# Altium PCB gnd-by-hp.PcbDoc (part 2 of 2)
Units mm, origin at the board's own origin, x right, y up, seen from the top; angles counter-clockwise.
Board outline 80 x 100 mm, 4 copper layers (Top Layer, Mid-Layer 1, Internal Plane 1, Bottom Layer); 158 components, 114 nets, 565 pads, 335 vias.
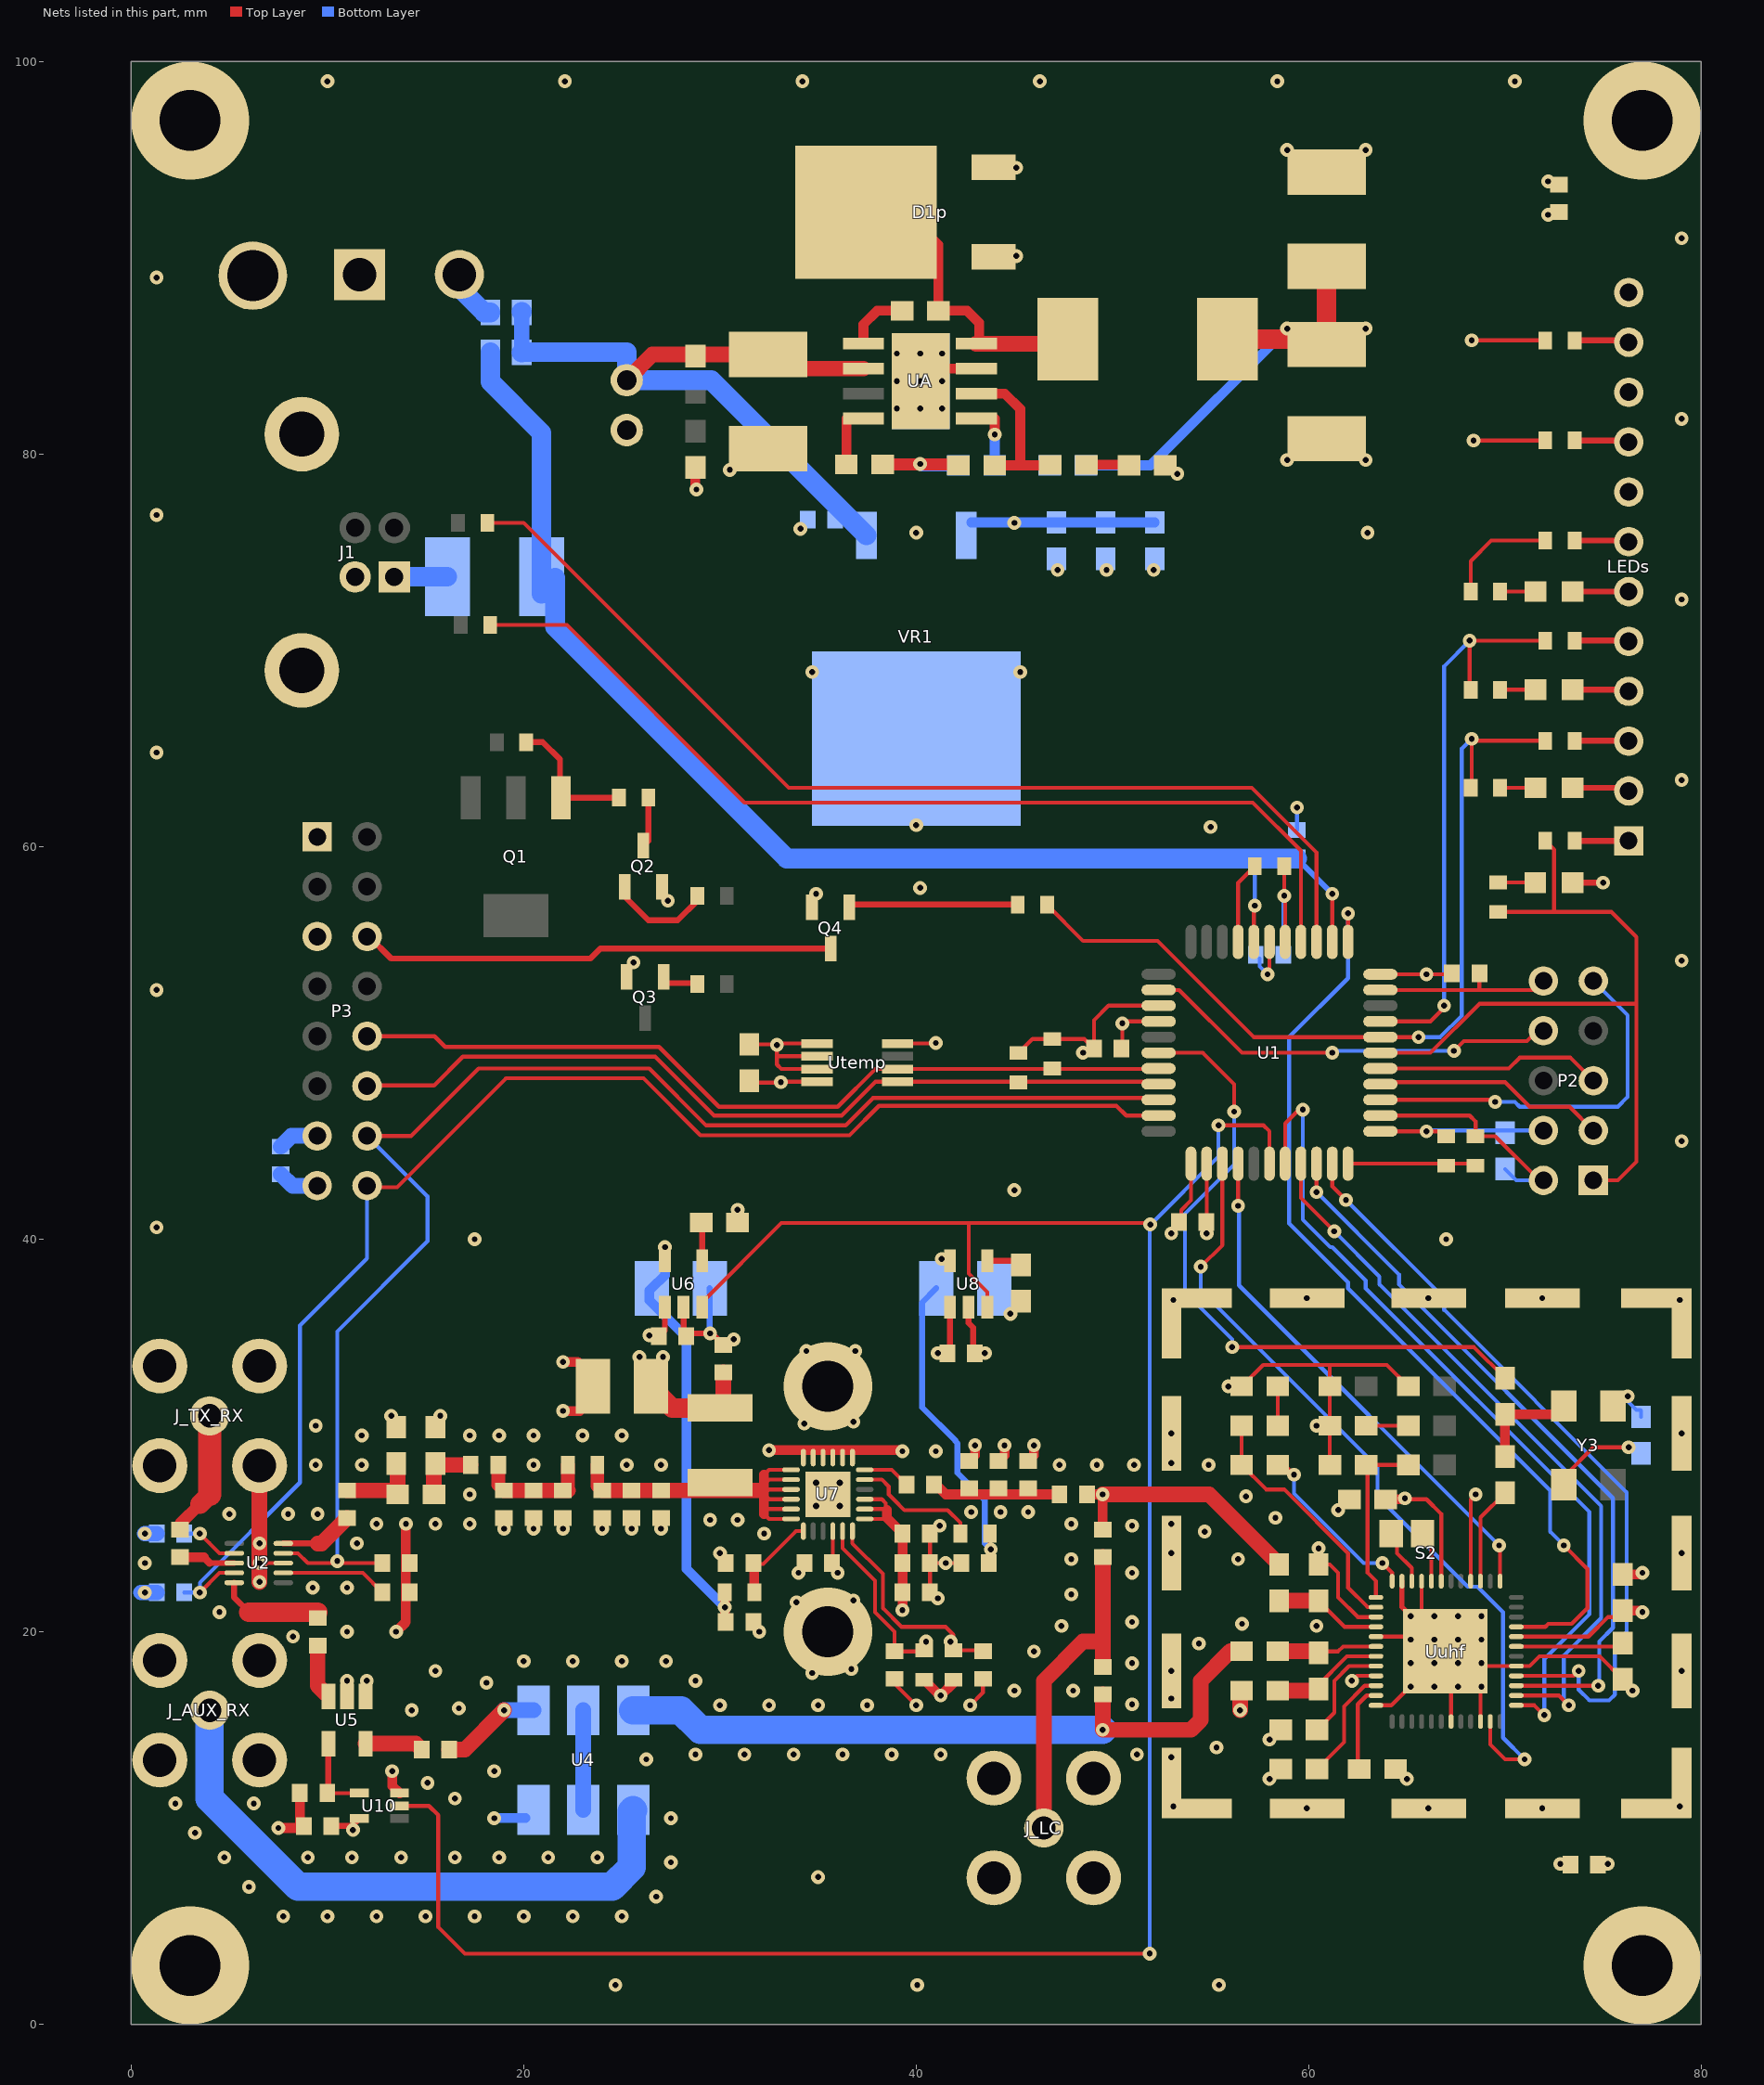
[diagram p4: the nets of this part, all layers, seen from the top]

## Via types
v1: diameter 0.7, hole 0.3, Top Layer to Bottom Layer, 290 vias
v2: diameter 0.7, hole 0.3, Top Layer to Bottom Layer, tented top, 19 vias
v3: diameter 0.6, hole 0.3, Top Layer to Bottom Layer, tented top, 16 vias
v4: diameter 6, hole 3.1, Top Layer to Bottom Layer, 4 vias
v5: diameter 0.66, hole 0.33, Top Layer to Bottom Layer, tented top, 4 vias
v6: diameter 4.5, hole 2.6, Top Layer to Bottom Layer, 2 vias

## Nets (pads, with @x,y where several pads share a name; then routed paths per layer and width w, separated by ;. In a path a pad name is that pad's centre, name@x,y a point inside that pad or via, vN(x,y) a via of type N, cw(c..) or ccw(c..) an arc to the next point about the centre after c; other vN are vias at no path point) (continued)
GND: C2.1 C2p.1 C3.1 C3p.1 C4.1 C4p.1 C5.1 C5p.1 C6.1 C6p.2 C7.2 C8.2 C9.1 C10.1 C11.1 C12h.1 C13.1 C14.1 C15.1 C16.1 C18.2 C19.1 C24.2 C25.2 C26.2 C27.2 C31.1 C32.1 C33.1 C34.1 C35.1 C36.1 C39.2 C40.1 C41.1 C42.2 C43.2 C44.2 C45.2 C45h.1 C46.2 C46h.1 C47.1 C48.2 C49.2 C50.1 C51.1 C52.1 C53.1 C54.1 C55.1 C56.1 C57.1 C59.1 C61.1 C62.1 C64.1 C65.1 C66.2 C67.1 C68.1 C69.1 D1p.1 D1p.3 J1.4 J1.5 J1.6 J_AUX_RX.2 J_AUX_RX.3 J_AUX_RX.4 J_AUX_RX.5 J_LC.2 J_LC.3 J_LC.4 J_LC.5 J_TX_RX.2 J_TX_RX.3 J_TX_RX.4 J_TX_RX.5 L2.1 L3.1 L4.1 P1.1 P2.2 P2.10 P3.1 P3.5 P3.15 pad.0 Q2.2 Q3.2 Q4.2 R3p.1 R4p.1 R5p.2 R11.2 R12.1 R15.1 R29.1 S2.0 U1.5 U1.15 U1.23 U1.35 U1.43 U2.3 U4.6 U5.1 U5.2 U6.2 U7.7 U7.8 U7.9 U7.10 U7.11 U7.12 U7.25 U8.2 U10.3 UA.7 UA.9 Utemp.4 Utemp.5 Utemp.6 Utemp.7 Uuhf.5 Uuhf.12 Uuhf.19 Uuhf.22 Uuhf.29 Uuhf.45 Uuhf.47 Uuhf.49 VR1.2 Y3.2 | length 162.8
  Top Layer w0.2: v1(6.54,23.5) U2.3@7.75,23.5 ; C65.1@31.5,49.925 32.825,49.925 v1@32.9,50 ; 32.925,49.325 Utemp.6@34.95,49.325 ; Utemp.7@34.95,48.675 33.125,48.675 32.9,48.9 v1@32.9,50 ; Utemp.5@34.95,49.975 32.925,49.975 v1@32.9,50 ; C45.2@38.9,17.6 38.9,17.35 v1(40,16.25) ; Utemp.4@39.05,49.975 40.975,49.975 v1(41,50) ; C49.2@40.7,22 C46.2@40.7,23.5 ; C43.2@40.7,25 C46.2@40.7,23.5 ; v1(41.5,23.5) C48.2@42.3,23.5 C46.2@40.7,23.5 ; v1(42.75,16.25) 43.4,16.9 C47.1@43.4,17.6 ; C6.1@50.459,49.708 50.5,49.749 v1(50.5,51) 50.6,51.1 U1.15@52.35,51.1 ; v1(53,40.3) 53.377,40.677 C5.1@53.377,40.869 ; C5.1@53.5,40.9 53.5,41.48 54,41.98 U1.23@54,43.85 ; v1(55.9,32.5) C18.2@56.575,32.5 57.675,33.6 61.1,33.6 ; R29.1@58.75,59 v1(58.75,57.5) 58.8,57.45 U1.5@58.8,55.15 ; v1(60.4,30.5) C56.1@61.075,30.5 ; C57.1@61.075,28.5 C56.1@61.075,30.5 ; v1(61.5,26.2) 61.529,26.2 C59.1@62.075,26.746 ; Uuhf.12@63.425,16.25 64.2,16.25 Uuhf.49@66.95,19 ; Uuhf.5@63.425,19.75 65.05,19.75 v3(65.2,19.6) ; U1.35@63.65,46.3 68.2,46.3 68.5,46 R15.1@68.5,45.25 69.5,45.25 71.75,43 P2.2@71.96,43 ; U1.43@63.65,52.7 68.7,52.7 ; C15.1@65.075,32.5 63.975,33.6 61.1,33.6 ; Uuhf.45@65.75,22.575 65.75,20.2 Uuhf.49@66.95,19 ; Uuhf.19@67.25,15.425 67.25,18.7 Uuhf.49@66.95,19 ; C8.2@68.696,53.543 68.696,52.704 68.7,52.7 ; Uuhf.22@68.75,15.425 68.75,17.15 v3(68.8,17.2) ; P2.10@71.96,53.16 71.5,52.7 68.7,52.7 ; v1(72.2,93.9) 72.36,93.74 C9.1@72.746,93.74 ; v1(72.822,8.166) 72.847,8.141 C68.1@73.341,8.141 ; C10.1@76,17.575 74.825,18.75 71.75,18.75 71.25,18.25 Uuhf.29@70.575,18.25 67.7,18.25 Uuhf.49@66.95,19 ; C56.1@61.075,30.5 C55.1@61.075,32.5 61.075,33.575 61.1,33.6
  Top Layer w0.25: Uuhf.47@64.75,22.575 64.75,21.25 v3(65.2,20.8)
  Top Layer w0.3: U6.2@28.143,36.544 28.143,35.193 C54.1@28.284,35.052 28.432,35.2 v1(29.5,35.2) 29.584,35.2 C51.1@30.175,34.609 ; C19.1@30.897,40.843 30.897,41.597 v1@30.9,41.6 ; U8.2@42.672,36.544 42.672,35.728 42.9,35.5 42.9,34.279 C53.1@42.966,34.214 ; C53.1@42.991,34.188 43.488,34.188 v1(43.5,34.2) ; v1(44.8,36.2) 45.339,36.739 C52.1@45.339,36.845
  Top Layer w0.5: v1(7.5,10) C67.1@8.705,10 ; C67.1@8.596,10.108 C66.2@8.596,11.786 ; v1(13.3,12.9) 13.3,12.149 U10.3@13.674,11.775 ; v1(13.5,20) 14,20.5 v1(14,25.5) ; v2(22,31.25) 22.85,31.25 C42.2@23.525,31.925 ; v2(22,33.75) 22.75,33.75 23.525,32.975 C42.2@23.525,32.5 ; R4p.1@28.751,79.32 28.751,78.249 v1(28.8,78.2) ; v1(32.5,29.25) 39.25,29.25 v1(39.3,29.2) ; Q4.2@34.69,56.905 34.69,57.39 v1(34.9,57.6) ; UA.9@40.232,83.725 40.867,84.36 UA.7@43.061,84.36 ; L2.1@42.7,28.7 43,29 v1(43,29.5) ; L3.1@44.2,28.7 44.5,29 v1(44.5,29.5) ; L4.1@45.7,28.7 46,29 v1(46,29.5) ; C11.1@76,22.925 76.925,22.925 v1(77,23)
  Top Layer w0.6: C5p.1@38.288,79.477 42.107,79.477 C6p.2@42.151,79.432
  Top Layer w0.8: v1(6.54,22.54) v1(6.54,23.5) v1(6.54,24.5) J_TX_RX.3@6.54,28.46 ; v1(56.5,16) 56.5,16.925 C12h.1@56.575,17
  Bottom Layer w0.2: C7.2@58.7,54.5 58.7,57.45 v1(58.75,57.5) ; C69.1@59.394,60.847 59.4,60.853 v1(59.4,62) ; C13.1@70,43.575 70.575,43 P2.2@71.96,43 ; v2(76.25,32) 76.25,31.75 76.7,31.3 76.9,31.3 76.937,31.263 C16.1@76.937,30.948
  Bottom Layer w0.3: C39.2@29.475,37.5 29.475,35.225 v1(29.5,35.2)
  Bottom Layer w0.5: v1(18.5,10.5) U4.6@20.08,10.5
  Bottom Layer w0.6: v1@40.268,79.432 R3p.1@42.151,79.432
  Bottom Layer w0.8: v1(0.7,22) C27.2@1.3,22 ; v1(0.7,25) C26.2@1.3,25 ; C64.1@7.626,43.318 8.221,42.723 P3.15@9.48,42.723
  other v1: 24.675,2 40.051,2 55.426,2 7.75,5.5 10,5.5 12.5,5.5 15,5.5 17.5,5.5 20,5.5 22.5,5.5 25,5.5 26.75,6.5 6,7 35,7.5 27.5,8.25 4.75,8.5 9,8.5 11.25,8.5 13.75,8.5 16.5,8.5 18.75,8.5 21.25,8.5 23.75,8.5 27.5,10.5 16.5,11.5 15.1,12.3 58,12.5 65,12.5 18.5,12.9 26.25,13.5 53,13.6 28.75,13.75 31.25,13.75 33.75,13.75 36.25,13.75 38.75,13.75 41.25,13.75 51.25,13.75 55.3,14.1 58,14.5 30,16.25 32.5,16.25 35,16.25 37.5,16.25 51,16.3 53,16.6 45,17 48,17 76.5,17 18.1,17.4 28.75,17.5 34.7,17.9 15.5,18 36.7,18.1 51,18.4 20,18.5 22.5,18.5 25,18.5 27.25,18.5 46,19 54.4,19.4 8.25,19.75 11,20 32,20 47.4,20.3 60.4,20.3 56.6,20.4 51,20.5 4.5,21 33.9,21.5 36.8,21.6 41.1,21.7 47.9,21.9 9.25,22.25 11,22.25 34,23 51,23 0.7,23.5 47.9,23.7 56.4,23.7 30,24 11.5,24.5 32.25,25 54.7,25.1 19,25.25 20.5,25.25 22,25.25 24,25.25 25.5,25.25 27,25.25 41.2,25.4 51,25.4 12.5,25.5 15.5,25.5 17.25,25.5 47.9,25.5 53,25.5 29.5,25.7 30.9,25.7 58.3,25.8 5,26 8,26 9.5,26 42.8,26.1 44.3,26.1 45.7,26.1 56.8,26.9 17.25,27 9.4,28.5 11.75,28.5 20.5,28.5 25.25,28.5 27,28.5 47.3,28.5 49.2,28.5 51.1,28.5 54.9,28.5 53,28.6 41,29.2 11.75,30 17.25,30 18.75,30 20.5,30 23,30 25,30 9.4,30.5 34.3,30.6 36.8,30.7 13.25,31 15.75,31 34.4,34.3 36.9,34.3 30.7,34.9 17.5,40 67,40 1.3,40.6 30.9,41.5 45,42.5 79,45 32.9,49.9 1.3,52.7 25.6,54.1 79,54.2 27.35,57.25 40.2,57.9 55,61 40,61.1 79,63.4 1.3,64.8 34.7,68.9 45.3,68.9 79,72.6 47.2,74.1 49.7,74.1 52.1,74.1 40,76 63,76 34.1,76.2 1.3,76.9 53.3,79 30.5,79.2 40.2,79.5 58.9,79.7 62.9,79.7 79,81.8 1.3,89 45.1,90.1 79,91 45.1,94.6 58.9,95.5 62.9,95.5 10,99 22.1,99 34.2,99 46.3,99 58.4,99 70.5,99
  other v2: 3.25,9.75 2.25,11.25 6.25,11.25 14.3,16 16.7,16.1 11,17.5 12,17.5
  other v3: 65.2,17.2 66.4,17.2 67.6,17.2 65.2,18.4 66.4,18.4 67.6,18.4 68.8,18.4 66.4,19.6 67.6,19.6 68.8,19.6 66.4,20.8 67.6,20.8 68.8,20.8
  other v4: 3,3 77,3 3,97 77,97
  other v5: 34.9,26.4 36.1,26.4 34.9,27.6 36.1,27.6
  other v6: 35.5,20 35.5,32.5
L1: L5.1 Uuhf.46 | length 2.9
  Top Layer w0.2: L5.1@64.2,25 64.5,24.7 64.5,24 65.25,23.25 Uuhf.46@65.25,22.575
L2: L5.2 Uuhf.44 | length 2.6
  Top Layer w0.2: L5.2@65.8,25 66.25,24.55 Uuhf.44@66.25,22.575
LED_P: R5.1 R19.2 U1.41 | length 29.3
  Top Layer w0.2: U1.41@63.65,51.1 66.2,51.1 67,51.9 v1(66.9,51.9) ; R19.2@68.25,68 68.2,68.05 v1(68.2,70.5) R5.1@72.05,70.5
  Bottom Layer w0.2: v1(66.9,51.9) 66.9,69.2 v1(68.2,70.5)
LED_R: R4.1 R18.2 R34.2 U1.40 | length 45.2
  Top Layer w0.2: R34.2@46.662,57.038 48.5,55.2 52.3,55.2 57.2,50.3 U1.40@63.65,50.3 v1(65.6,50.3) ; R18.2@68.25,63 68.2,63.05 68.3,63.15 v1@68.3,65.4 ; R4.1@72.05,65.4 v1@68.3,65.4 ; v1@68.3,65.4 v1(68.3,65.5) 68.2,65.4 v1@68.3,65.4
  Bottom Layer w0.2: v1(65.6,50.3) 66.7,50.3 67.8,51.4 67.8,65 v1(68.3,65.5)
LED_T: P2.1 R3.1 R17.2 U1.39 | length 39.5
  Top Layer w0.2: U1.39@63.65,49.5 66.2,49.5 68.7,52 76.7,52 ; R17.2@69.647,56.679 72.5,56.679 ; R3.1@72.05,60.3 72.5,59.85 72.5,56.679 ; P2.1@74.5,43 75.75,43 76.7,43.95 76.7,52 ; 72.5,56.679 75.421,56.679 76.7,55.4 76.7,52
LED_U1: P2.3 R6.1 R20.2 U1.37 | length 17.7
  Top Layer w0.2: U1.37@63.65,47.9 63.75,48 70,48 71.25,46.75 73.29,46.75 P2.3@74.5,45.54 ; R20.2@68.25,73 68.25,74.55 69.3,75.6 R6.1@72.05,75.6
LED_U2: R7.1 | length 3.7
  Top Layer w0.2: v1(68.4,80.7) R7.1@72.05,80.7
LED_U3: R8.1 | length 3.8
  Top Layer w0.2: v1(68.3,85.8) R8.1@72.05,85.8
LNA_V: C66.1 U5.4 U10.4 | length 4.3
  Top Layer w0.2: C66.1@10.05,12.045 9.881,11.876 9.981,11.775 U10.4@11.624,11.775
  Top Layer w0.3: C66.1@10.05,12.045 U5.4@10.05,14.3
MUXOUT: U1.26 Uuhf.37 | length 26.8
  Top Layer w0.2: v1(56.4,41.7) U1.26@56.4,43.85 ; v1(69.7,24.4) 69.75,24.35 Uuhf.37@69.75,22.575
  Bottom Layer w0.2: v1(56.4,41.7) 56.45,41.65 56.45,37.65 v1(69.7,24.4)
NetC1p_1: C1p.1 UA.1 | length 3.2
  Top Layer w0.5: UA.1@37.311,85.63 37.311,86.589 37.3,86.6 38.006,87.306 C1p.1@39.281,87.306
NetC5p_2: C5p.2 UA.4 | length 2.3
  Top Layer w0.5: C5p.2@36.438,79.477 UA.4@36.438,81.8
NetC6p_1: C6p.1 C7p.1 UA.6 | length 8.2
  Top Layer w0.5: UA.6@43.061,83.09 44.51,83.09 45.3,82.3 45.3,79.5 ; C6p.1@44.001,79.432 46.8,79.432 C7p.1@46.825,79.458
NetC7_1: C7.1 U1.6 | length 2.3
  Top Layer w0.2: v2@58,53.8 58,54 U1.6@58,55.15
  Bottom Layer w0.2: C7.1@57.5,54.3 57.5,53.9 v2(57.9,53.5)
NetC7p_2: C7p.2 R5p.1 | length 2.2
  Top Layer w0.5: C7p.2@48.675,79.458 50.813,79.458 R5p.1@50.838,79.432
NetC9h_2: C9h.2 L1h.2 Uuhf.6 | length 5.2
  Top Layer w0.2: L1h.2@60.425,19 61.5,19 61.75,19.25 Uuhf.6@63.425,19.25
  Top Layer w0.8: C9h.2@58.425,19 60.425,19 L1h.2@60.5,18.925
NetC10_2: C10.2 Uuhf.31 | length 5.5
  Top Layer w0.2: Uuhf.31@70.575,19.25 75.825,19.25 C10.2@76,19.425
NetC12_2: C12.2 U5.5 | length 3
  Top Layer w0.8: U5.5@11.95,14.3 14.5,14.3 C12.2@14.8,14
NetC12h_2: C12h.2 L1h.1 Uuhf.7 | length 5.9
  Top Layer w0.2: L1h.1@60.425,17 60.425,17.225 61.95,18.75 Uuhf.7@63.425,18.75
  Top Layer w0.8: C12h.2@58.425,17 L1h.1@60.425,17
NetC14_2: C14.2 Uuhf.11 | length 4.4
  Top Layer w0.2: C14.2@62.575,13 62.5,13.075 62.5,16.3 62.95,16.75 Uuhf.11@63.425,16.75
NetC17_1: C17.1 R13.1 Uuhf.2 | length 12.9
  Top Layer w0.2: R13.1@56.575,30.5 C17.1@56.575,28.5 57.825,27.25 58.75,27.25 62,24 62,22.25 63,21.25 Uuhf.2@63.425,21.25
NetC17_2: C17.2 Uuhf.48 | length 9.1
  Top Layer w0.2: C17.2@58.425,28.5 58.75,28.5 v1(59.25,28) ; v1(63.75,23.5) 64.25,23 Uuhf.48@64.25,22.575
  Bottom Layer w0.2: v1(59.25,28) 59.25,27.05 62.8,23.5 v1(63.75,23.5)
NetC18_1: C18.1 R13.2 | length 2
  Top Layer w0.2: R13.2@58.425,30.5 C18.1@58.425,32.5
NetC19_2: C19.2 U6.4 | length 2
  Top Layer w0.3: C19.2@29.047,40.843 29.093,40.797 U6.4@29.093,38.894
NetC20_1: C20.1 C30.1 Y3.3 | length 5.3
  Top Layer w0.5: C30.1@70,28.925 C20.1@70,31.075 72.575,31.075 Y3.3@73,31.5
NetC21_1: C21.1 C46h.2 L5h.2 | length 4.3
  Top Layer w0.8: C21.1@11,27.2 13.375,27.2 L5h.2@13.575,27 13.575,28.5 C46h.2@13.5,28.575
NetC21_2: C21.2 U2.5 | length 3.8
  Top Layer w0.3: U2.5@7.75,24.5 9.5,24.5
  Top Layer w0.8: 9.5,24.5 9.7,24.5 C21.2@11,25.8
NetC22_1: C22.1 U2.8 | length 2.9
  Top Layer w0.3: 4,23.5 U2.8@5.25,23.5
  Top Layer w0.4: 3.7,23.8 4,23.5
  Top Layer w0.5: C22.1@2.5,23.8 3.7,23.8
NetC23_1: C23.1 U5.3 | length 2.6
  Top Layer w0.8: C23.1@9.5,19.3 9.5,17.25 U5.3@9.875,16.875
NetC24_1: C24.1 U2.2 | length 5.5
  Top Layer w0.2: U2.2@7.75,23 11.8,23 C24.1@12.8,22
NetC26_1: C26.1 U2.7 | length 3
  Top Layer w0.2: v1(3.5,25) 4,24.5 4.5,24 U2.7@5.25,24
  Bottom Layer w0.2: C26.1@2.7,25 v1(3.5,25)
NetC29_1: C29.1 C34.2 C35.2 C36.2 R16.2 | length 6
  Top Layer w0.5: C36.2@18.7,27.5 C36.2@19,27.2
  Top Layer w0.7: C36.2@18.7,27.5 C29.1@18.7,28.5 ; C34.2@22.25,27.2 R16.2@22.25,28.5
  Top Layer w0.8: C36.2@19,27.2 C35.2@20.5,27.2 C34.2@22.25,27.2
NetC30_2: C30.2 Uuhf.39 | length 5
  Top Layer w0.2: Uuhf.39@68.75,22.575 68.75,25.825 C30.2@70,27.075
NetC37_1: C37.1 C38.2 L2.2 L3.2 L4.2 | length 6.6
  Top Layer w0.5: C38.2@40.9,27.5 41,27.5 41.5,27 45,27 C37.1@47.3,27
NetC38_1: C38.1 U7.6 | length 2.4
  Top Layer w0.2: U7.6@37.375,28.25 38.75,28.25 C38.1@39.5,27.5
NetC42h_1: C42h.1 L4h.1 Uuhf.4 | length 5.5
  Top Layer w0.2: L4h.1@60.5,21.575 61.825,20.25 Uuhf.4@63.425,20.25
  Top Layer w0.8: C42h.1@58.5,21.575 L4h.1@60.5,21.575
NetC45_1: C45.1 R21.1 U7.23 | length 8.7
  Top Layer w0.2: U7.23@36.25,25.125 36.25,24.25 37.9,22.6 37.9,21 38.9,20 C45.1@38.9,19 40.35,19 R21.1@40.4,19.05
  other v1: 40.5,19.5
NetC47_2: C47.2 R22.1 U7.24 | length 11
  Top Layer w0.2: U7.24@36.75,25.125 36.75,24.5 38.3,22.95 38.3,21.2 39.25,20.25 41.5,20.25 41.9,19.85 R22.1@41.9,19.05 43.35,19.05 C47.2@43.4,19
  other v1: 41.75,19.5
NetC50_2: C50.2 R23.2 U7.19 | length 4.7
  Top Layer w0.2: C50.2@31.75,23.45 32.2,23.45 33.875,25.125 U7.19@34.25,25.125
  Top Layer w0.5: C50.2@31.7,23.5 31.75,23.45 R23.2@31.75,22
NetC52_2: C52.2 U8.4 | length 1.8
  Top Layer w0.3: U8.4@43.622,38.894 45.14,38.894 C52.2@45.339,38.695
NetC56_2: C56.2 R9.1 | length 2.2
  Top Layer w0.2: C56.2@62.925,30.5 R9.1@65.075,30.5
NetD1_2: D1.2 R17.1 | length 1.9
  Top Layer w0.2: R17.1@69.647,58.179 71.528,58.179 D1.2@71.542,58.166
NetD2_2: D2.2 R18.1 | length 1.8
  Top Layer w0.2: R18.1@69.75,63 D2.2@71.55,63
NetD3_2: D3.2 R19.1 | length 1.8
  Top Layer w0.2: R19.1@69.75,68 D3.2@71.55,68
NetD4_2: D4.2 R20.1 | length 1.8
  Top Layer w0.2: R20.1@69.75,73 D4.2@71.55,73
NetJ1_1: J1.1 MF.2 | length 2.7
  Bottom Layer w0.2: J1.1@13.41,73.75 J1.1@13.42,73.76
  Bottom Layer w1: J1.1@13.42,73.76 MF.2@16.111,73.76
NetLEDs_1: LEDs.1 R3.2 | length 2.7
  Top Layer w0.3: R3.2@73.55,60.3 LEDs.1@76.3,60.3
NetLEDs_3: LEDs.3 R4.2 | length 2.8
  Top Layer w0.3: R4.2@73.55,65.4 76.28,65.4 LEDs.3@76.3,65.38
NetLEDs_5: LEDs.5 R5.2 | length 2.8
  Top Layer w0.3: R5.2@73.55,70.5 76.26,70.5 LEDs.5@76.3,70.46
NetLEDs_7: LEDs.7 R6.2 | length 2.8
  Top Layer w0.3: R6.2@73.55,75.6 76.24,75.6 LEDs.7@76.3,75.54
NetLEDs_9: LEDs.9 R7.2 | length 2.8
  Top Layer w0.3: R7.2@73.55,80.7 76.22,80.7 LEDs.9@76.3,80.62
NetLEDs_11: LEDs.11 R8.2 | length 2.8
  Top Layer w0.3: R8.2@73.55,85.8 76.2,85.8 LEDs.11@76.3,85.7
NetQ1_1: Q1.1 R25.1 R26.1 | length 7
  Top Layer w0.3: R25.1@20.13,65.329 20.971,65.329 21.85,64.45 21.85,62.55 Q1.1@21.9,62.5 R26.1@24.85,62.5
NetQ2_1: Q2.1 R27.1 | length 5.4
  Top Layer w0.3: Q2.1@25.15,57.95 25.15,57.45 26.35,56.25 27.85,56.25 28.85,57.25 R27.1@28.85,57.5
NetQ2_3: Q2.3 R26.2 | length 2.6
  Top Layer w0.3: Q2.3@26.1,60.05 26.35,60.3 R26.2@26.35,62.5
NetQ3_1: Q3.1 R28.1 | length 1.7
  Top Layer w0.3: Q3.1@27.15,53.05 28.8,53.05 R28.1@28.85,53
NetQ4_1: Q4.1 R34.1 | length 8.7
  Top Layer w0.3: Q4.1@36.59,56.905 36.734,57.048 R34.1@45.2,57.048
NetR1_2: R1.2 U1.3 | length 53.8
  Top Layer w0.2: R1.2@18.15,76.5 20,76.5 33.5,63 57.1,63 60.4,59.7 U1.3@60.4,55.15
NetR2_2: R2.2 U1.4 | length 50.7
  Top Layer w0.2: R2.2@18.296,71.296 22.204,71.296 31.25,62.25 57.15,62.25 59.6,59.8 U1.4@59.6,55.15
NetR11_1: R11.1 Uuhf.8 | length 5.3
  Top Layer w0.2: R11.1@60.425,15 61.3,15.875 61.3,17.5 62.05,18.25 Uuhf.8@63.425,18.25
NetR12_2: R12.2 Uuhf.10 | length 5.8
  Top Layer w0.2: R12.2@60.425,13 61.8,14.375 61.8,16.2 62.85,17.25 Uuhf.10@63.425,17.25
NetR24_1: R24.1 U7.5 | length 6.6
  Top Layer w0.2: U7.5@37.375,27.75 38.25,27.75 38.6,27.4 38.6,27 38.9,26.7 39.4,26.2 41.6,26.2 42.25,25.55 R24.1@42.25,25
NetR29_2: R29.2 U1.8 | length 4.2
  Top Layer w0.2: U1.8@56.4,55.15 56.4,58.15 R29.2@57.25,59
NetU4_2: U4.2 U4.5 | length 5.1
  Bottom Layer w0.8: U4.5@23.04,10.92 U4.2@23.04,16
PA_BIAS_EN: U1.28 U6.3 U8.3 U10.2 | length 122.4
  Top Layer w0.2: U10.2@13.674,11.125 15.175,11.125 15.65,10.65 15.65,4.95 17,3.6 v1(51.9,3.6) ; U6.3@29.093,36.407 U6.3@29.093,36.544 29.093,36.793 33.125,40.825 42.675,40.825 ; U8.3@43.7,36.466 U8.3@43.622,36.544 43.622,37.303 42.675,38.25 42.675,40.825 ; v1(51.925,40.75) 51.85,40.825 42.675,40.825 ; v1(55.4,45.8) 57.7,45.8 58,45.5 U1.28@58,43.85
  Bottom Layer w0.2: v1(51.9,3.6) 51.9,40.7 55.4,44.2 v1(55.4,45.8)
PA_IN: C28.1 C37.2 C42h.2 | length 13.1
  Top Layer w0.5: C37.2@48.7,27 v1(49.5,27) C28.1@49.5,25.2
  Top Layer w0.8: v1(49.5,27) 54.925,27 C42h.2@58.5,23.425
PA_OUT: C29.2 C45h.2 L5h.1 | length 3.4
  Top Layer w0.8: L5h.1@15.425,27 15.425,28.5 C45h.2@15.5,28.575 15.575,28.5 C29.2@17.3,28.5
PE2: R14.1 R15.2 U1.33 | length 6.5
  Top Layer w0.2: U1.33@62,43.85 68.4,43.85 R15.2@68.5,43.75
PHA: C1p.2 D1p.4 LA.1 UA.8 | length 12.3
  Top Layer w0.5: D1p.4@40.6,91.2 41.131,90.669 C1p.2@41.131,87.306 42.594,87.306 43.2,86.7 43.2,85.769 UA.8@43.061,85.63
  Top Layer w0.8: UA.8@43.061,85.63 47.496,85.63 LA.1@47.725,85.859
PTT_TX_STAGE_1: P3.6 Q4.3 | length 24.2
  Top Layer w0.3: P3.6@12.12,55.423 13.243,54.3 23.4,54.3 23.905,54.805 Q4.3@35.64,54.805
RESET: P2.8 U1.13 | length 21.4
  Top Layer w0.2: U1.13@52.35,52.7 53.4,52.7 56.6,49.5 v1(61.2,49.5) ; v1(67.4,49.6) 67.9,50.1 71.11,50.1 71.63,50.62 P2.8@71.96,50.62
  Bottom Layer w0.2: v1(61.2,49.5) 61.3,49.6 v1(67.4,49.6)
RF_LC: C28.2 C58.2 J_LC.1 | length 16.9
  Top Layer w0.8: J_LC.1@46.5,10 46.5,17.5 48.5,19.5 49.5,19.5 ; C58.2@49.5,18.2 49.5,19 C28.2@49.5,23.8
RF_RX: C23.2 U2.10 | length 5.3
  Top Layer w0.3: U2.10@5.25,22.5 5.25,21.75 6,21
  Top Layer w1: 6,21 C23.2@9.5,21
RF_RX_AUX: J_AUX_RX.1 U4.4 | length 31.2
  Bottom Layer w1.44: J_AUX_RX.1@4,16 4,11.5 8.5,7 24.5,7 25.5,8 25.5,10.84 U4.4@25.58,10.92
RF_RX_C: C27.1 P3.16 U1.21 U2.9 | length 72
  Top Layer w0.2: v1(3.5,22) 4.5,23 U2.9@5.25,23 ; P3.16@11.9,42.653 13.553,42.653 19.1,48.2 26.1,48.2 29,45.3 36.6,45.3 38.1,46.8 50.2,46.8 50.7,46.3 U1.21@52.35,46.3
  Bottom Layer w0.2: C27.1@2.7,22 v1(3.5,22) 3.5,22.5 8.6,27.6 8.6,35.6 12.02,39.02 P3.16@12.02,42.723
RF_RX_LNA: C12.1 U4.1 | length 5.1
  Top Layer w0.8: C12.1@16.2,14 17,14 v1(19,16)
  Bottom Layer w0.8: v1(19,16) U4.1@20.5,16
RF_RX_MOD: C9h.1 C58.1 U4.3 | length 36
  Top Layer w0.8: C58.1@49.5,16.8 v1(49.5,15) 54,15 54.5,15.5 54.5,17.5 56,19 C9h.1@56.575,19
  Bottom Layer w1.44: U4.3@25.58,16 28,16 29,15 v1(49.5,15)
RF_RX_TX: C22.2 J_TX_RX.1 | length 6.4
  Top Layer w0.5: C22.2@2.5,25.2 C22.2@2.5,25.5
  Top Layer w0.6: C22.2@2.5,25.5 3.5,26.5
  Top Layer w1: 3.5,26.5 4,27
  Top Layer w1.2: 4,27 J_TX_RX.1@4,31
RF_TX_C: C25.1 P3.14 U1.20 U2.4 | length 73.7
  Top Layer w0.2: U2.4@7.75,24 8.5,24 9,23.5 C25.1@12.8,23.5 ; P3.14@12.02,45.263 14.263,45.263 17.7,48.7 26.4,48.7 29.3,45.8 36.4,45.8 37.8,47.2 52.25,47.2 U1.20@52.35,47.1
  Bottom Layer w0.2: v1(10.5,23.6) 10.5,35.3 15.1,39.9 15.1,42.183 P3.14@12.02,45.263
RFOUT: C31.2 C32.2 C33.2 L1.1 R16.1 U7.13 U7.14 U7.15 U7.16 U7.17 U7.18 | length 20.7
  Top Layer w0.2: 32.25,26 32.5,25.75 U7.18@33.625,25.75 ; 32.25,26.25 U7.17@33.625,26.25 ; 32.25,27.5 32.5,27.75 U7.14@33.625,27.75 ; 32.25,28 32.5,28.25 U7.13@33.625,28.25 ; U7.16@33.625,26.75 32.5,26.75 32.25,27 32.5,27.25 U7.15@33.625,27.25
  Top Layer w0.5: C31.2@23.75,27.45 C31.2@24,27.2 ; L1.1@29.6,27.2 L1.1@30,27.6 ; 32.25,26 32.25,26.25 32.25,27 32.25,27.5 32.25,28
  Top Layer w0.7: C31.2@23.75,27.45 R16.1@23.75,28.5
  Top Layer w0.8: C31.2@24,27.2 C32.2@25.5,27.2 C33.2@27,27.2 32,27.2
SCCLK: U1.32 Uuhf.28 | length 39.9
  Top Layer w0.2: U1.32@61.2,43.85 61.2,42.7 v1(61.9,42) ; Uuhf.28@70.575,17.75 73.5,17.75 v1(73.75,18)
  Bottom Layer w0.2: v1(61.9,42) 66.9,37 66.9,36.4 76.2,27.1 76.2,20 75.6,19.4 75.6,16.8 75.3,16.5 74.3,16.5 73.75,17.05 v1(73.75,18)
SCL: P3.10 R31.1 U1.18 Utemp.2 | length 42.5
  Top Layer w0.2: P3.10@12.157,50.343 15.457,50.343 16,49.8 26.9,49.8 29.95,46.75 36,46.75 37.925,48.675 Utemp.2@39.05,48.675 52.325,48.675 U1.18@52.35,48.7
SDA: P3.12 R30.1 U1.19 Utemp.1 | length 42.9
  Top Layer w0.2: P3.12@12.02,47.836 15.436,47.836 16.9,49.3 26.7,49.3 29.7,46.3 36.2,46.3 37.925,48.025 Utemp.1@39.05,48.025 52.225,48.025 U1.19@52.35,47.9
SDATA: U1.30 Uuhf.26 | length 37.7
  Top Layer w0.2: U1.30@59.6,43.85 59.6,42.1 v1(61.3,40.4) ; Uuhf.26@70.575,16.75 72.75,16.75 v1(73.25,16.25)
  Bottom Layer w0.2: v1(61.3,40.4) 63.6,38.1 63.6,37.7 74.9,26.4 74.9,20.7 73,18.8 73,16.5 v1(73.25,16.25)
SLE: U1.29 Uuhf.25 | length 42.8
  Top Layer w0.2: U1.29@58.8,43.85 58.8,45.9 59.5,46.6 v1(59.7,46.6) ; Uuhf.25@70.575,16.25 71.5,16.25 v1(72,15.75)
  Bottom Layer w0.2: v1(59.7,46.6) 59.7,41 61.1,39.6 61.2,39.6 62.9,37.9 62.9,37.5 74.3,26.1 74.3,20.9 72,18.6 v1(72,15.75)
SREAD: U1.31 Uuhf.27 | length 37.3
  Top Layer w0.2: v2(60.4,42.4) U1.31@60.4,43.85 ; Uuhf.27@70.575,17.25 v1(74.75,17.25)
  Bottom Layer w0.2: v2(60.4,42.4) 64.6,38.2 64.6,37.7 75.5,26.8 75.5,20.2 74.8,19.5 74.8,17.3 v1(74.75,17.25)
SWD: U1.1 Uuhf.33 | length 48.6
  Top Layer w0.2: U1.1@62,55.15 v2@62,56.8 ; Uuhf.33@70.575,20.25 72.05,20.25 72.2,20.4 73.4,20.4 74.2,21.2 74.2,23.2 v1(73,24.4)
  Bottom Layer w0.2: v2(62,56.6) 62,53.3 59,50.3 59,40.8 62,37.8 62,37.5 72.3,27.2 72.3,25.1 v1(73,24.4)
TDI_MOSI: P2.9 U1.36 | length 19.6
  Top Layer w0.2: U1.36@63.65,47.1 69.4,47.1 v1(69.5,47)
  Bottom Layer w0.2: v1(69.5,47) 70.5,47 70.75,46.75 75.75,46.75 76.25,47.25 76.25,51.41 P2.9@74.5,53.16
TEST_A: U1.25 Uuhf.23 | length 41.2
  Top Layer w0.2: v1(54.5,38.6) 55.6,39.7 U1.25@55.6,43.85 ; Uuhf.23@69.25,15.425 69.25,14.25 70,13.5 v1(71,13.5)
  Bottom Layer w0.2: v1(54.5,38.6) 54.5,37.4 63.5,28.4 63.5,26.9 64.7,25.7 68.1,22.3 68.6,22.3 69.9,21 69.9,14.6 v1(71,13.5)
TMS_RST: P2.5 U1.38 | length 11.6
  Top Layer w0.2: U1.38@63.65,48.7 70.2,48.7 70.75,49.25 73.33,49.25 P2.5@74.5,48.08
V_BUS: C69.2 MF.1 R32.1 U1.2 U1.7 | length 68.8
  Top Layer w0.2: U1.7@57.2,55.15 v1@57.2,56.95 ; U1.2@61.2,55.15 v1(61.2,57.6)
  Bottom Layer w0.2: v1@57.25,57.25 57.25,59.45
  Bottom Layer w0.3: C69.2@59.4,59.4 v1(61.2,57.6)
  Bottom Layer w1: R32.1@18.301,85.192 18.301,83.699 20.911,81.089 MF.1@20.911,74.1 ; MF.1@20.911,74.411 MF.1@20.911,73.76 20.911,72.889 21.323,73.3 MF.1@21.323,72.977 ; MF.1@21.6,73.7 21.6,71.2 33.4,59.4 C69.2@59.4,59.4
  other v1: 57.25,57
VCC: C2.2 C2p.2 C3.2 C3p.2 C4.2 C5.2 C6.2 C8.1 C9.2 C11.2 C13.2 C16.2 C42.1 C43.1 C44.1 C46.1 C49.1 C51.2 C53.2 C54.2 C59.2 C64.2 C65.2 C67.2 C68.2 D1.1 D2.1 D3.1 D4.1 L1.2 L4h.2 LA.2 LEDs.2 LEDs.4 LEDs.6 LEDs.8 LEDs.10 LEDs.12 P2.4 P3.13 R1p.2 R14.2 R21.2 R22.2 R30.2 R31.2 U1.14 U1.24 U1.34 U1.44 U6.1 U7.1 U7.2 U7.3 U7.22 U8.1 U10.5 Utemp.8 Uuhf.3 Uuhf.9 Uuhf.32 Uuhf.40 Uuhf.43 VR1.3 Y3.4 | length 128.8
  Top Layer w0.2: C65.2@31.5,47.975 33.175,47.975 33.25,48 33.275,48.025 Utemp.8@34.95,48.025 ; C44.1@35.7,23.5 35.75,23.55 U7.22@35.75,25.125 ; U7.1@37.375,25.75 38.45,25.75 38.5,25.8 ; U7.2@37.375,26.25 38.45,26.25 ; U7.3@37.375,26.75 38.25,26.75 38.45,26.55 38.45,26.25 ; 38.5,26.2 38.45,26.25 ; R30.2@45.212,49.493 45.923,50.204 R31.2@46.939,50.204 48.563,50.204 C6.2@49.059,49.708 ; v1(48.5,49.5) 48.708,49.708 C6.2@49.059,49.708 ; U1.14@52.35,51.9 49.8,51.9 49.059,51.159 C6.2@49.059,49.708 ; C5.2@54.777,40.869 54.777,40.323 v1(54.8,40.3) ; C5.2@54.8,40.8 U1.24@54.8,43.85 ; v1(60.5,24.25) L4h.2@60.5,23.425 61.075,23.425 61.5,23 61.5,21.75 62.5,20.75 Uuhf.3@63.425,20.75 ; v1@62.4,17.7 62.45,17.75 Uuhf.9@63.425,17.75 ; U1.34@63.65,45.5 R14.2@66.75,45.5 ; U1.44@63.65,53.5 v1(66,53.5) 67.253,53.5 C8.1@67.296,53.543 ; v1@64.8,26.8 64.85,26.75 66,26.75 66.75,26 Uuhf.43@66.75,22.575 ; Uuhf.40@68.25,22.575 68.25,26.75 v1(68.5,27) ; Uuhf.32@70.575,19.75 74.25,19.75 75.25,20.75 75.675,20.75 C11.2@76,21.075 ; Y3.4@73,27.5 73,27.9 74.5,29.4 v1(76.3,29.4) ; C68.2@74.741,8.141 75.21,8.141 v1(75.235,8.166)
  Top Layer w0.3: C67.2@10.205,10.1 11.249,10.1 U10.5@11.624,10.475 ; v2(26.4,35.1) 26.836,35.1 C54.2@26.884,35.052 27.193,35.361 U6.1@27.193,36.544 ; v1(41.1,34.2) 41.112,34.188 C53.2@41.591,34.188 41.722,34.319 U8.1@41.722,36.544 ; D1.1@73.442,58.166 v1(75,58.166) ; D2.1@73.45,63 76.14,63 LEDs.2@76.3,62.84 ; D3.1@73.45,68 LEDs.4@76.3,68 ; D4.1@73.45,73 LEDs.6@76.3,73
  Top Layer w0.5: 38.5,26.2 38.5,25.8 C43.1@39.3,25 C46.1@39.3,23.5 C49.1@39.3,22 v1(39.3,21.1) ; R21.2@40.4,17.55 41.2,16.75 v2(41.25,16.75) 41.9,17.4 R22.2@41.9,17.55 ; C59.2@63.925,26.746 63.929,26.75 v1@64.85,26.75 ; C11.2@76,21.075 76.925,21.075 v1(77,21)
  Top Layer w0.8: L1.2@30,31.4 30.175,31.575 C51.2@30.175,33.209
  Top Layer w1: C42.1@26.475,32.5 27.575,31.4 L1.2@30,31.4 ; LA.2@55.853,85.859 C2p.2@60.64,85.859 ; C2p.2@60.907,85.592 C2p.2@60.64,85.859 ; C3p.2@60.909,89.573 60.909,86.128 C2p.2@60.64,85.859
  Bottom Layer w0.2: v1(66,45.5) 66.25,45.5 66.29,45.54 P2.4@71.96,45.54
  Bottom Layer w0.5: VR1.3@42.8,76.525 C2.2@47.15,76.525 C3.2@49.65,76.525 C4.2@52.15,76.525 ; R1p.2@48.65,79.432 51.932,79.432 v1(58.9,86.4)
  Bottom Layer w0.8: C64.2@7.626,44.718 8.17,45.263 P3.13@9.48,45.263
  other v1: 11.3,9.9 62.2,17.5 36,23 64.9,26.8 33.1,48 45,76.5 62.9,86.4 72.2,92.2
  other v2: 25.9,34 27.1,34
VCC_AUX: C4p.2 C61.2 C62.2 R2p.2 R32.2 R33.2 UA.2 VR1.1 | length 37.3
  Top Layer w0.8: C61.2@25.25,83.77 26.564,85.084 C4p.2@32.459,85.084 33.183,84.36 UA.2@37.311,84.36
  Bottom Layer w0.8: R33.2@19.9,87.265 R33.2@19.903,87.262 ; R33.2@19.901,87.224 R32.2@19.901,85.192 19.901,85.182 R32.2@19.903,85.179
  Bottom Layer w1: R32.2@19.903,85.179 19.928,85.204 25.25,85.204 C61.2@25.25,83.77 29.558,83.77 VR1.1@37.465,75.863 ; R33.2@19.903,87.262 R33.2@19.915,87.25
VCC_POWER_DC: P1.2 R33.1 | length 2.8
  Bottom Layer w1: P1.2@16.2,89 17.976,87.224 R33.1@18.301,87.224
VCOIN: C57.2 R10.1 Uuhf.1 | length 9.1
  Top Layer w0.2: Uuhf.1@63.425,21.75 63.425,22.575 63,23 63,28.425 C57.2@62.925,28.5 R10.1@65.075,28.5
VREG1: C39.1 C40.2 R23.1 U6.5 | length 21.8
  Top Layer w0.5: R23.1@30.25,22 30.25,20.55 C40.2@30.3,20.5
  Bottom Layer w0.5: v1(27.2,39.6) 27.2,38.175 C39.1@26.525,37.5 26.4,37.375 26.4,36.9 28.3,35 28.3,23.2 v1(30.25,21.25)
VREG2: C41.2 C48.1 R24.2 U8.5 | length 17
  Top Layer w0.2: C48.1@43.7,23.5 43.75,23.55 R24.2@43.75,25
  Top Layer w0.3: v1(41.3,39) 41.616,39 U8.5@41.722,38.894
  Bottom Layer w0.3: C41.2@41.025,37.5 40.3,36.775 40.3,31.438 42,29.738 42,29.7 42.1,29.6 42.1,28.1 43.5,26.7 43.5,24.5 v1(43.8,24.2)
VSENSEA: R1p.1 R3p.2 UA.5 | length 5.2
  Top Layer w0.5: v1(44,81) UA.5@44,81.8
  Bottom Layer w0.5: v1@44.001,80.999 R3p.2@44.001,79.432 R1p.1@46.8,79.432
X1: C20.2 U1.17 | length 34.5
  Top Layer w0.2: U1.17@52.35,49.5 54.6,49.5 56.2,47.9 v1(56.2,46.5) ; v1(56.1,34.5) 68.425,34.5 C20.2@70,32.925
  Bottom Layer w0.2: v1(56.1,34.5) 56.1,34.9 53.7,37.3 53.7,41.3 56.2,43.8 v1(56.2,46.5)
pads on no net: P2.6 P2.7 P3.9 P3.11 U1.16 U1.42 U2.1 U2.6 U7.4 U7.20 U7.21 U10.1 Utemp.3 Uuhf.13 Uuhf.14 Uuhf.15 Uuhf.16 Uuhf.17 Uuhf.18 Uuhf.20 Uuhf.21 Uuhf.30 Uuhf.38 Y3.1
copper on no net: | length 9.2
  Top Layer w0.2: 66.25,15.425 66.25,14.5 66,14.25 66,13.5 66.5,13 v1(66.75,12.75) ; v1(66.75,14) 66.75,15.425 ; v1(67.75,13.5) 67.75,15.425 ; 68.25,15.425 68.25,14 68.5,13.75 v1(68.5,12.75)
  other v1: 9.3,2 70.802,2

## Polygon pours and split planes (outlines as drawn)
VCC on Mid-Layer 1 "supply" (solid, pour order 1000): 1,1 1,99.6 79.1,99.6 79.1,1
GND on Internal Plane 1 (split plane): 79.49,0.51 0.51,0.51 0.51,99.49 79.49,99.49

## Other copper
Multi-Layer:
  the board outline again, w0.254

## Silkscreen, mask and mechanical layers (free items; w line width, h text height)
Top Overlay:
  lines w0.4: 38,57 43,57 ; 38,57 38,62 ; 38,57 38,62 ; 38,62 43,62 ; 38,62 39.5,63.5 44.5,63.5 ; 43,57 43,62 ; 43,57 44.5,58.5 44.5,63.5 ; 43,62 44.5,63.5 ; 43,62 44.5,63.5
  text "-DC+" at 6.8,93.2 h2
  text "BlueBox Rev. 1B" at 19.2,70.4 h3
  text "http://www.satlab.org" at 21.4,66.6 h2
  text "ANT" at 1.5,35.7 h2
  text "PT" at 0.8,9.8 h1.5
  text "+33dBm Pout" at 54,6.4 h1.4
  text "RF DEBUG" at 39.7,3.7 h1.5
  text "2013 (c) HPM" at 13,1.3 h1.5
